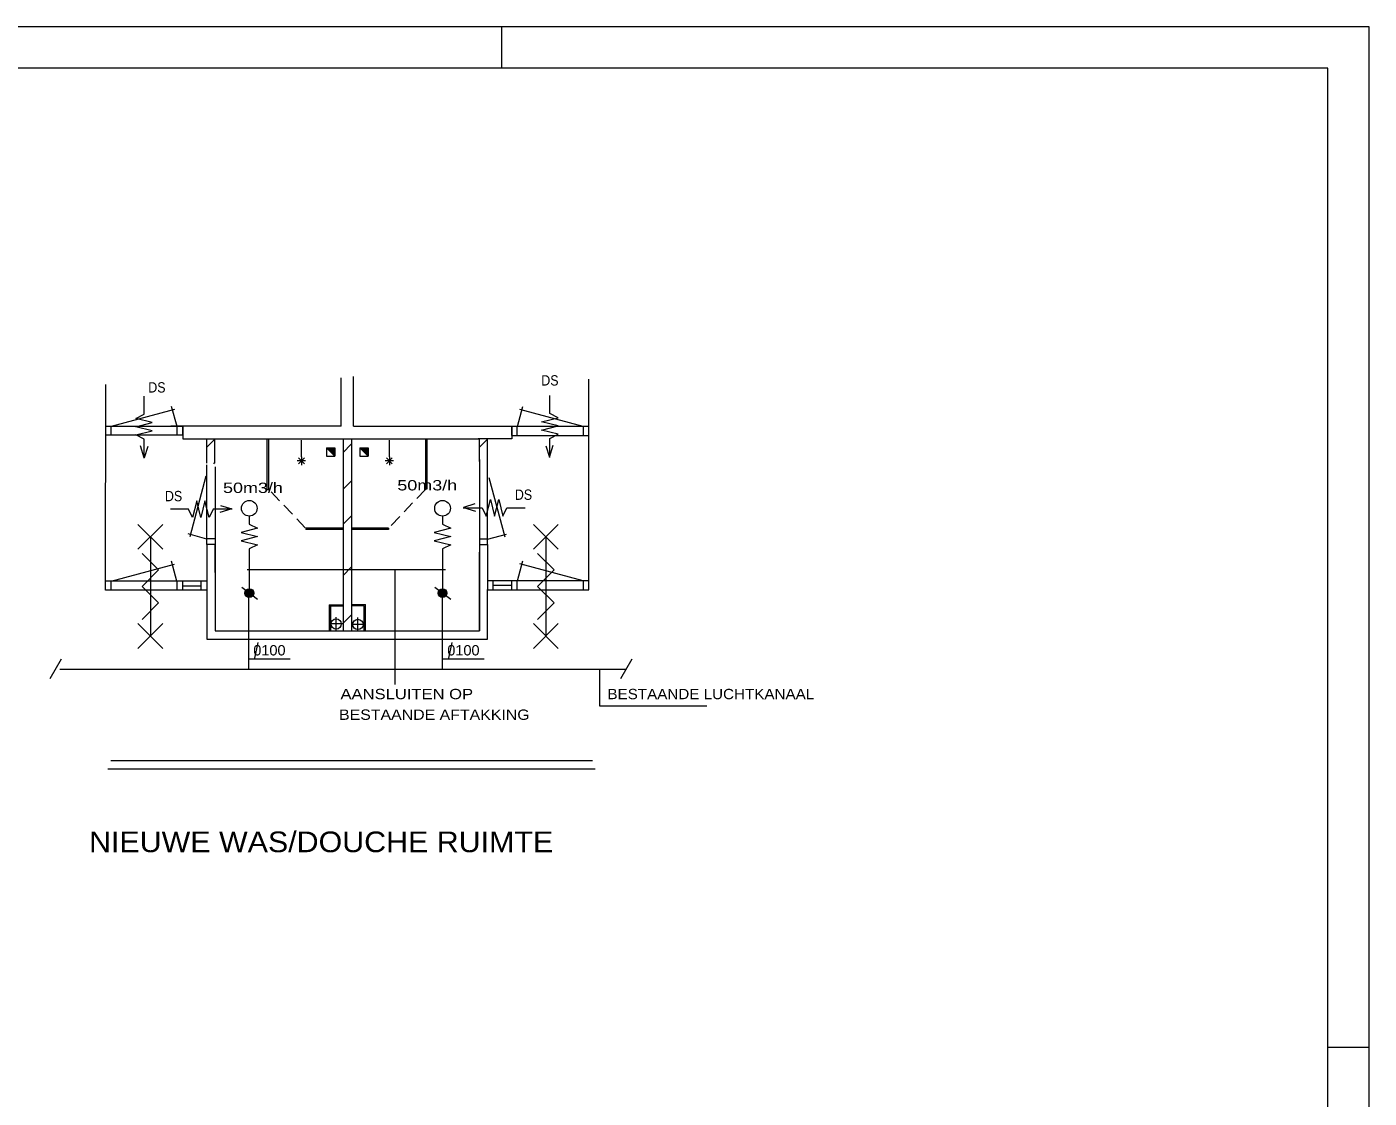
# Model space of a CAD drawing. Extents: x 295824 to 414724, y 24924 to 109024.
# Drawn here: x 382224 to 414724, y 83088 to 109024 of the extents above; entities that cross this region are included whole.
import ezdxf

# ---------------------------------------------------------------- set-up
doc = ezdxf.new("R2010")
doc.units = 0
doc.header["$LTSCALE"] = 100
doc.linetypes.add('DOT_DASHED', pattern=[7.7, 5, -1.2, 0.3, -1.2])
doc.linetypes.add('MEDIUM_DASHED', pattern=[4.5, 3, -1.5])
for name, color, linetype, lineweight in [('1', 7, 'Continuous', 13), ('16', 7, 'Continuous', 13), ('24', 7, 'Continuous', 13)]:
    doc.layers.add(name, color=color, linetype=linetype, lineweight=lineweight)

msp = doc.modelspace()

# ---------------------------------------------------------------- hatches: boundary and pattern name
at = {"layer": '1'}
for points in [[(389679, 98633.9), (389479, 98833.9), (389679, 98833.9)], [(390485.1, 98633.9), (390285.1, 98833.9), (390485.1, 98833.9)]]:
    msp.add_hatch(color=256, dxfattribs=at).paths.add_polyline_path(points)
at = {"layer": '24'}
for points in [[(387718.6, 95313.5, 1), (387501.4, 95313.5, 1)], [(392396.9, 95313.5, 1), (392179.7, 95313.5, 1)]]:
    msp.add_hatch(color=256, dxfattribs=at).paths.add_polyline_path(points)

# ---------------------------------------------------------------- linework, layer by layer
at = {"layer": '1'}
for p, q in [((393723.6, 108023.8), (393723.6, 109023.8)), ((414723.6, 24923.8), (414723.6, 109023.8)), ((389830.9, 99352.6), (389830.9, 100528.9)), ((390130.8, 99352.6), (390130.8, 100562.2)), ((395829.7, 95615.8), (395829.7, 100497.7)), ((384131.4, 95608), (384134.7, 100362.2)), ((385859.9, 99350.9), (385729.9, 99836.3)), ((394103.5, 99346.9), (394233.6, 99832.4)), ((384270.8, 99355.2), (385805.4, 99766.4)), ((395692.7, 99351.2), (394158.1, 99762.4)), ((385995.4, 99135.6), (384133.8, 99135.6)), ((384265.6, 99134.9), (384265.6, 99354.9)), ((389830.9, 99352.6), (385710.9, 99352.6)), ((385865.6, 99134.9), (385865.6, 99354.9)), ((385999.6, 99134.9), (385999.6, 99354.9)), ((390130.8, 99352.6), (394015.8, 99352.6)), ((390130.9, 99352.6), (395829.5, 99352.6)), ((393963.9, 99130.9), (393963.9, 99350.9)), ((393968.1, 99131.6), (395829.7, 99131.6)), ((394097.9, 99130.9), (394097.9, 99350.9)), ((395697.9, 99130.9), (395697.9, 99350.9)), ((395829.7, 99131.6), (395829.7, 99352.4)), ((386001.4, 99052.6), (393181.7, 99052.6)), ((386581, 98458.8), (386581, 99052.6)), ((386581, 98851.1), (386781.9, 99051.9)), ((386778.5, 98464.4), (386778.5, 99052.6)), ((388046.4, 97825.9), (388046.4, 99042.8)), ((388082.4, 97825.9), (388082.4, 99042.8)), ((388872.1, 98615.1), (388872.1, 99015.1)), ((389880.8, 99052.6), (389880.8, 97815.1)), ((389881.8, 98722.8), (390078.8, 98919.7)), ((390080.8, 99052.6), (390080.8, 98575.6)), ((391001.1, 98615.1), (391001.1, 99015.1)), ((391882, 97838.2), (391882, 99047.8)), ((391918, 97838.2), (391918, 99047.8)), ((393181.7, 98504.7), (393181.7, 99053.3)), ((393182, 98851.1), (393382.9, 99051.9)), ((393381.3, 98521.4), (393381.3, 99052.6)), ((386749.9, 98447.2), (386779.1, 98476.5)), ((388972.1, 98515.1), (388772.1, 98515.1)), ((388942.9, 98585.8), (388801.4, 98444.3)), ((388942.9, 98444.3), (388801.4, 98585.8)), ((388872.1, 98615.1), (388872.1, 98415.1)), ((390080.8, 98629.6), (390080.8, 94402.6)), ((391101.1, 98515.1), (390901.1, 98515.1)), ((391071.8, 98585.8), (390930.4, 98444.3)), ((391071.8, 98444.3), (390930.4, 98585.8)), ((391001.1, 98615.1), (391001.1, 98415.1)), ((393180.8, 98548.4), (393180.8, 96491.8)), ((393381.1, 97693.5), (393381.1, 98570.2)), ((386580.6, 96492.5), (386580.6, 98417.9)), ((386780.6, 98374.4), (386780.6, 96492.5)), ((386560.9, 98144.1), (386167.3, 96674.9)), ((388046.4, 97825.9), (388082.4, 97825.9)), ((389880.8, 97979.6), (389880.8, 94402.6)), ((389881.8, 97827.6), (390078.8, 98024.6)), ((391882, 97838.2), (391918, 97838.2)), ((393408, 98115.3), (393794.1, 96674.2)), ((393380.8, 96490.2), (393380.8, 97786)), ((389881.8, 96982.5), (390078.8, 97179.5)), ((384914.7, 96376.2), (385514.7, 96976.2)), ((385514.7, 96376.2), (384914.7, 96976.2)), ((389880.1, 96854.2), (388979.4, 96854.2)), ((390982.9, 96890.2), (390082.8, 96890.2)), ((390982.9, 96854.2), (390082.8, 96854.2)), ((390982.9, 96890.2), (390982.9, 96854.2)), ((394490, 96376.2), (395090, 96976.2)), ((395090, 96376.2), (394490, 96976.2)), ((385214.7, 96676.2), (385214.7, 94276.2)), ((386581.1, 96624.5), (386126.5, 96746.3)), ((386780.3, 96626.5), (386581.6, 96626.5)), ((393181.1, 96625.8), (393379.8, 96625.8)), ((393380.3, 96623.8), (393834.9, 96745.6)), ((394790, 96676.2), (394790, 94276.2)), ((386780.6, 96492.5), (386580.6, 96492.5)), ((386580.8, 96487.4), (386580.8, 94913.2)), ((386780.8, 95813.2), (386780.8, 96487.4)), ((393180.8, 96491.8), (393380.8, 96491.8)), ((393380.8, 96491.8), (393380.8, 95602.6)), ((384268.4, 95606.9), (385802.9, 96018.1)), ((385857.5, 95602.6), (385727.4, 96088.1)), ((389881.8, 95742.7), (390078.8, 95939.6)), ((394103.5, 95610.3), (394233.6, 96095.8)), ((395692.7, 95614.7), (394158.1, 96025.9)), ((384263.2, 95386.6), (384263.2, 95606.6)), ((385863.2, 95386.6), (385863.2, 95606.6)), ((385997.2, 95386.6), (385997.2, 95606.6)), ((386448.2, 95386.6), (386448.2, 95606.6)), ((393512.9, 95394.3), (393512.9, 95614.3)), ((393963.9, 95394.3), (393963.9, 95614.3)), ((394097.9, 95394.3), (394097.9, 95614.3)), ((395697.9, 95394.3), (395697.9, 95614.3)), ((385998.8, 95488.1), (386448.2, 95488.1)), ((386580.8, 95402.6), (386580.8, 94202.6)), ((387587, 95224.3), (387587, 93470.2)), ((392280.7, 95224.3), (392280.7, 93470.2)), ((393380.8, 94202.6), (393380.8, 95402.6)), ((393962.2, 95495.9), (393512.9, 95495.9)), ((389544.3, 95034.6), (389879.8, 95034.6)), ((389544.3, 95034.6), (389544.3, 94407.1)), ((389574.3, 95004.6), (389882.2, 95004.6)), ((389574.3, 95004.6), (389574.3, 94406.6)), ((390082.2, 95037.4), (390420.5, 95037.4)), ((390390.7, 95007), (390083.9, 95007)), ((390390.7, 94403.8), (390390.7, 95007)), ((390420.5, 94402.6), (390420.5, 95037.4)), ((384914.7, 93976.2), (385514.7, 94576.2)), ((385514.7, 93976.2), (384914.7, 94576.2)), ((389884.6, 94586.6), (390079.2, 94781.1)), ((394490, 93976.2), (395090, 94576.2)), ((395090, 93976.2), (394490, 94576.2)), ((390130.5, 94402.6), (390508.7, 94402.6)), ((390157.6, 94402.6), (393180.8, 94402.6)), ((386580.8, 94202.6), (390530.9, 94202.6)), ((387820, 94121), (387736.7, 93737.7)), ((390049, 94202.6), (393380.8, 94202.6)), ((392517.1, 94121), (392433.8, 93737.7)), ((387586.8, 93721), (388602.9, 93721)), ((392283.9, 93721), (393299.9, 93721)), ((389830.1, 91054.7), (384187.8, 91054.7)), ((395921.8, 91254.7), (384254.4, 91254.7)), ((395981.7, 91054.7), (389419.8, 91054.7)), ((413723.6, 84323.8), (414723.6, 84323.8))]:
    msp.add_line(p, q, dxfattribs=at)
at = {"layer": '1', "linetype": 'MEDIUM_DASHED'}
for p, q in [((388964.7, 96896.3), (388081, 97826.4)), ((391873.2, 97822.9), (390985.2, 96888.3))]:
    msp.add_line(p, q, dxfattribs=at)
at = {"layer": '1', "linetype": 'DOT_DASHED'}
for p, q in [((389712.1, 94406.4), (389712.1, 94734.5)), ((390239.8, 94405.4), (390239.8, 94724.1)), ((389890.5, 94568.8), (389562.4, 94568.8)), ((390410, 94553.9), (390081.9, 94553.9)), ((390410.3, 94553.9), (390082.2, 94553.9))]:
    msp.add_line(p, q, dxfattribs=at)
at = {"layer": '1'}
for points in [[(414723.6, 109023.8), (304995.6, 109023.8), (295823.6, 109023.8)], [(304995.6, 25923.8), (413723.6, 25923.8), (413723.6, 108023.8), (304995.6, 108023.8)], [(384133.8, 99135.6), (384133.8, 99356.4), (386000.5, 99356.3)], [(389830.8, 99352.6), (386001.4, 99352.6), (386001.4, 99052.6)], [(393963, 99352.4), (393963, 99052.6), (393152.2, 99052.6)], [(389479, 98833.9), (389679, 98833.9), (389679, 98633.9)], [(390285.1, 98833.9), (390485.1, 98833.9), (390485.1, 98633.9)], [(386780.8, 96854.2), (386780.8, 94402.6), (390540.8, 94402.6)], [(389880.1, 96890.2), (388979.4, 96890.2), (388979.4, 96854.2)], [(385014.7, 96276.2), (385414.7, 95876.2), (385014.7, 95476.2), (385414.7, 95076.2), (385014.7, 94676.2)], [(393180.8, 96491.8), (393180.8, 94402.6), (393180.8, 96302.6)], [(394590, 96276.2), (394990, 95876.2), (394590, 95476.2), (394990, 95076.2), (394590, 94676.2)]]:
    msp.add_lwpolyline(points, dxfattribs=at)
for points in [[(389479, 98833.9), (389479, 98633.9), (389679, 98633.9)], [(389679, 98633.9), (389479, 98833.9), (389679, 98833.9)], [(390285.1, 98833.9), (390285.1, 98633.9), (390485.1, 98633.9)], [(390485.1, 98633.9), (390285.1, 98833.9), (390485.1, 98833.9)], [(384131.4, 95387.3), (384131.4, 95608), (386580, 95608), (386580, 95387.3)], [(395829.7, 95395), (395829.7, 95615.8), (393381.1, 95615.8), (393381.1, 95395)]]:
    msp.add_lwpolyline(points, close=True, dxfattribs=at)
for centre in [(389712.1, 94567.1), (390241.1, 94555.3)]:
    msp.add_circle(centre, 125, dxfattribs=at)
at = {"layer": '16'}
for p, q in [((395084.9, 99360.4), (394684.9, 99460.4)), ((384861.1, 99343.8), (385261.1, 99443.8)), ((386436.5, 97147.4), (386336.5, 97547.4)), ((393548.6, 97180.7), (393648.6, 97580.7))]:
    msp.add_line(p, q, dxfattribs=at)
at = {"layer": '24'}
for p, q in [((385067.9, 98592.9), (384977.9, 98881.3)), ((385152.7, 98864.6), (385067.9, 98592.9)), ((394793.3, 98881.2), (394878.1, 98609.6)), ((394878.1, 98609.6), (394968.2, 98898)), ((387187.3, 97354.2), (386898.9, 97264.1)), ((386915.7, 97439), (387187.3, 97354.2)), ((393069.4, 97472.3), (392797.8, 97387.5)), ((392797.8, 97387.5), (393086.1, 97297.4)), ((387609.9, 96284.3), (387609.9, 95267.5)), ((392288.3, 96284.3), (392288.3, 95267.5)), ((387560.2, 95889), (392360.9, 95889)), ((391137.8, 95858.4), (391137.8, 93104.5)), ((387426.7, 95455.2), (387809.8, 95171.8)), ((392105.1, 95455.2), (392488.2, 95171.8)), ((383052.8, 93715), (382779.7, 93241.9)), ((396873.9, 93715), (396598.7, 93238.3)), ((383022.2, 93470.2), (396732.6, 93470.2))]:
    msp.add_line(p, q, dxfattribs=at)
for points in [[(394684.9, 99460.4), (395084.9, 99560.4), (394884.9, 99660.4), (394884.9, 100097.9)], [(385261.1, 99443.8), (384861.1, 99543.8), (385061.1, 99643.8), (385061.1, 100081.2)], [(385061.1, 98581.3), (385061.1, 99043.8), (384861.1, 99143.8), (385261.1, 99243.8), (384861.1, 99343.8)], [(394884.9, 98597.9), (394884.9, 99060.4), (395084.9, 99160.4), (394684.9, 99260.4), (395084.9, 99360.4)], [(386336.5, 97547.4), (386236.5, 97147.4), (386136.5, 97347.4), (385699, 97347.4)], [(387199, 97347.4), (386736.5, 97347.4), (386636.5, 97147.4), (386536.5, 97547.4), (386436.5, 97147.4)], [(392786.1, 97380.7), (393248.6, 97380.7), (393348.6, 97180.7), (393448.6, 97580.7), (393548.6, 97180.7)], [(393648.6, 97580.7), (393748.6, 97180.7), (393848.6, 97380.7), (394286.1, 97380.7)], [(387609.9, 97184.3), (387609.9, 96984.3), (387809.9, 96884.3), (387409.9, 96784.3), (387809.9, 96684.3), (387409.9, 96584.3), (387809.9, 96484.3), (387609.9, 96384.3), (387609.9, 96284.3)], [(392288.3, 97184.3), (392288.3, 96984.3), (392488.3, 96884.3), (392088.3, 96784.3), (392488.3, 96684.3), (392088.3, 96584.3), (392488.3, 96484.3), (392288.3, 96384.3), (392288.3, 96284.3)], [(396091.4, 93471.7), (396091.4, 92584.3), (398690.5, 92584.3)]]:
    msp.add_lwpolyline(points, dxfattribs=at)
for centre, radius in [((387609.9, 97367.6), 189.9), ((392288.3, 97367.6), 189.9), ((387610, 95313.5), 108.6), ((392288.3, 95313.5), 108.6)]:
    msp.add_circle(centre, radius, dxfattribs=at)

# ---------------------------------------------------------------- texts
for s, height, width, p in [('DS', 250, 0.9, (385164.3, 100170.6)), ('DS', 250, 0.9, (394679.7, 100340.2)), ('50m3/h', 250, 1.3, (386974.2, 97739.4)), ('50m3/h', 250, 1.3, (391193.9, 97800.6)), ('DS', 250, 0.9, (394040.1, 97572.4)), ('DS', 250, 0.9, (385567.8, 97539.1)), ('0100', 250, 1.05, (387707, 93806.1)), ('0100', 250, 1.05, (392404.1, 93806.1)), (' AANSLUITEN OP ', 250, 1.2, (389706.9, 92746.4)), ('BESTAANDE LUCHTKANAAL', 250, 1.1, (396281.1, 92746.4)), (' BESTAANDE AFTAKKING', 250, 1.15, (389676.4, 92246.4)), ('NIEUWE WAS/DOUCHE RUIMTE', 500, 1.1, (383730.9, 89042.6))]:
    msp.add_text(s, height=height, dxfattribs=dict(at, width=width)).set_placement(p)

doc.saveas('drawing.dxf')
